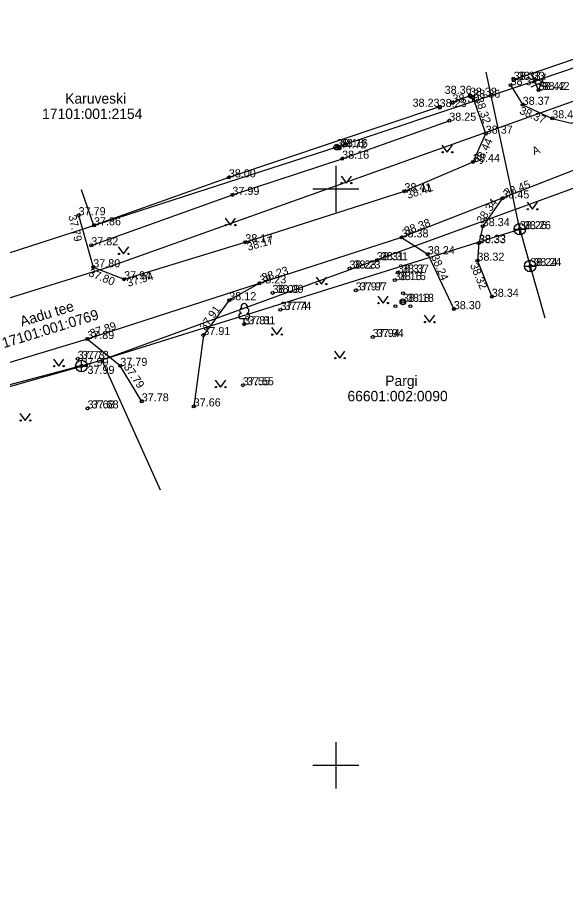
# Model space of a CAD drawing. Extents: x 627548 to 628052, y 6467984 to 6468802.
# Drawn here: x 627722.4 to 627769.9, y 6468388.4 to 6468464.9 of the extents above; entities that cross this region are included whole.
import ezdxf

# ---------------------------------------------------------------- set-up
doc = ezdxf.new("R2010")
doc.units = 0
for name, color, linetype in [('AED', 7, 'Continuous'), ('HALJASTUS', 7, 'Continuous'), ('KKAEV', 7, 'Continuous'), ('KORGUS-EH2000', 7, 'Continuous'), ('KTRASS', 7, 'Continuous'), ('MOOTKORG-EH2000', 7, 'Continuous'), ('MOOTKORGMUU-EH2000', 7, 'Continuous'), ('MOOTMPUNKT', 7, 'Continuous'), ('MPOHULIIN', 7, 'Continuous'), ('PIIR', 7, 'Continuous'), ('POST', 7, 'Continuous'), ('PUU', 7, 'Continuous'), ('SIOHULIIN', 7, 'Continuous'), ('TEE', 7, 'Continuous'), ('VORK', 7, 'Continuous')]:
    doc.layers.add(name, color=color, linetype=linetype)

msp = doc.modelspace()

# ---------------------------------------------------------------- linework, layer by layer
at = {"layer": 'AED'}
for p, q in [((627765.315, 6468459.596), (627765.315, 6468459.346)), ((627765.315, 6468459.596), (627765.565, 6468459.596)), ((627765.565, 6468459.596), (627765.565, 6468459.346)), ((627765.315, 6468459.346), (627765.565, 6468459.346)), ((627761.635, 6468458.089), (627760.129, 6468457.507)), ((627761.51, 6468458.214), (627761.51, 6468457.964)), ((627761.51, 6468458.214), (627761.76, 6468458.214)), ((627761.51, 6468457.964), (627761.76, 6468457.964)), ((627761.76, 6468458.214), (627761.76, 6468457.964)), ((627758.89, 6468457.24), (627758.89, 6468456.99)), ((627758.89, 6468457.24), (627759.14, 6468457.24)), ((627759.14, 6468457.24), (627759.14, 6468456.99)), ((627760.004, 6468457.632), (627760.004, 6468457.382)), ((627760.004, 6468457.632), (627760.254, 6468457.632)), ((627760.004, 6468457.382), (627760.254, 6468457.382)), ((627760.254, 6468457.632), (627760.254, 6468457.382)), ((627758.89, 6468456.99), (627759.14, 6468456.99))]:
    msp.add_line(p, q, dxfattribs=at)
for points in [[(627793.589, 6468469.234), (627785.422, 6468466.301), (627773.403, 6468462.19), (627765.44, 6468459.471)], [(627759.015, 6468457.115), (627740.72, 6468451.002), (627729.018, 6468446.845), (627727.922, 6468449.929)]]:
    msp.add_lwpolyline(points, dxfattribs=at)
at = {"layer": 'HALJASTUS'}
for p, q in [((627759.218, 6468453.793), (627759.682, 6468453.187)), ((627759.682, 6468453.187), (627760.127, 6468453.793)), ((627750.461, 6468451.119), (627750.924, 6468450.512)), ((627750.924, 6468450.512), (627751.37, 6468451.119)), ((627766.611, 6468448.843), (627767.074, 6468448.236)), ((627767.074, 6468448.236), (627767.52, 6468448.843)), ((627740.395, 6468447.478), (627740.859, 6468446.871)), ((627740.859, 6468446.871), (627741.304, 6468447.478)), ((627731.126, 6468444.974), (627731.589, 6468444.367)), ((627731.589, 6468444.367), (627732.035, 6468444.974)), ((627748.3, 6468442.357), (627748.763, 6468441.75)), ((627748.763, 6468441.75), (627749.209, 6468442.357)), ((627753.645, 6468440.707), (627754.109, 6468440.1)), ((627754.109, 6468440.1), (627754.554, 6468440.707)), ((627757.683, 6468439.057), (627758.146, 6468438.45)), ((627758.146, 6468438.45), (627758.592, 6468439.057)), ((627744.433, 6468437.975), (627744.896, 6468437.369)), ((627744.896, 6468437.369), (627745.342, 6468437.975)), ((627749.892, 6468435.927), (627750.356, 6468435.32)), ((627750.356, 6468435.32), (627750.801, 6468435.927)), ((627725.496, 6468435.244), (627725.96, 6468434.638)), ((627725.96, 6468434.638), (627726.405, 6468435.244)), ((627739.542, 6468433.424), (627740.006, 6468432.817)), ((627740.006, 6468432.817), (627740.451, 6468433.424)), ((627722.596, 6468430.522), (627723.059, 6468429.915)), ((627723.059, 6468429.915), (627723.505, 6468430.522))]:
    msp.add_line(p, q, dxfattribs=at)
for centre in [(627759.281, 6468453.187), (627760.109, 6468453.187), (627750.523, 6468450.512), (627751.352, 6468450.512), (627766.673, 6468448.236), (627767.502, 6468448.236), (627740.458, 6468446.871), (627741.287, 6468446.871), (627731.188, 6468444.367), (627732.017, 6468444.367), (627748.362, 6468441.75), (627749.191, 6468441.75), (627753.708, 6468440.1), (627754.537, 6468440.1), (627757.745, 6468438.45), (627758.574, 6468438.45), (627744.495, 6468437.369), (627745.324, 6468437.369), (627749.955, 6468435.32), (627750.783, 6468435.32), (627725.559, 6468434.638), (627726.387, 6468434.638), (627739.605, 6468432.817), (627740.434, 6468432.817), (627722.658, 6468429.915), (627723.487, 6468429.915)]:
    msp.add_circle(centre, 0.055, dxfattribs=at)
at = {"layer": 'KKAEV'}
for p, q in [((627765.476, 6468446.513), (627766.476, 6468446.513)), ((627765.976, 6468446.013), (627765.976, 6468447.013)), ((627766.878, 6468442.815), (627766.878, 6468443.815)), ((627766.378, 6468443.315), (627767.378, 6468443.315)), ((627727.929, 6468434.138), (627727.929, 6468435.138)), ((627727.429, 6468434.638), (627728.429, 6468434.638))]:
    msp.add_line(p, q, dxfattribs=at)
for centre in [(627765.976, 6468446.513), (627766.878, 6468443.315), (627727.929, 6468434.638)]:
    msp.add_circle(centre, 0.5, dxfattribs=at)
at = {"layer": 'KTRASS'}
msp.add_line((627765.976, 6468446.513), (627763.045, 6468460.12), dxfattribs=at)
msp.add_lwpolyline([(627653.907, 6468388.368), (627643.967, 6468406.571), (627696.734, 6468425.803), (627727.929, 6468434.638), (627765.976, 6468446.513), (627766.878, 6468443.315), (627768.149, 6468438.807)], dxfattribs=at)
at = {"layer": 'MOOTMPUNKT'}
for centre in [(627765.44, 6468459.471), (627765.165, 6468459.007), (627767.597, 6468458.583), (627761.635, 6468458.089), (627761.937, 6468457.914), (627759.015, 6468457.115), (627760.129, 6468457.507), (627766.223, 6468457.303), (627759.851, 6468455.919), (627768.784, 6468456.128), (627763.015, 6468454.798), (627750.093, 6468453.636), (627750.336, 6468453.529), (627750.557, 6468452.624), (627761.916, 6468452.344), (627740.72, 6468451.002), (627741.031, 6468449.484), (627755.959, 6468449.801), (627764.457, 6468449.184), (627727.686, 6468447.721), (627729.018, 6468446.845), (627762.755, 6468446.775), (627765.976, 6468446.513), (627755.708, 6468445.797), (627728.782, 6468445.109), (627742.149, 6468445.377), (627762.41, 6468445.297), (627762.43, 6468445.327), (627757.987, 6468444.338), (627753.569, 6468443.816), (627762.293, 6468443.775), (627766.878, 6468443.315), (627728.953, 6468443.206), (627751.19, 6468443.098), (627755.401, 6468442.746), (627731.631, 6468442.165), (627743.362, 6468441.806), (627755.123, 6468442.092), (627744.517, 6468440.979), (627751.737, 6468441.197), (627740.758, 6468440.345), (627755.828, 6468440.207), (627763.543, 6468440.641), (627745.196, 6468439.512), (627760.245, 6468439.571), (627742.057, 6468438.259), (627738.51, 6468437.327), (627753.206, 6468437.151), (627728.433, 6468436.983), (627727.606, 6468435.254), (627727.929, 6468434.638), (627731.305, 6468434.655), (627741.937, 6468432.968), (627733.163, 6468431.571), (627737.672, 6468431.136), (627728.46, 6468430.96)]:
    msp.add_circle(centre, 0.125, dxfattribs=at)
at = {"layer": 'MPOHULIIN'}
for points in [[(627776.772, 6468462.547), (627750.093, 6468453.636)], [(627750.093, 6468453.636), (627697.787, 6468436.749)]]:
    msp.add_lwpolyline(points, dxfattribs=at)
at = {"layer": 'PIIR'}
for p, q in [((627796.61, 6468466.88), (627730.27, 6468443.22)), ((627775.14, 6468451.7), (627729.69, 6468435.15)), ((627730.27, 6468443.22), (627696.02, 6468432.54)), ((627697.47, 6468426.57), (627729.69, 6468435.15)), ((627729.69, 6468435.15), (627734.759, 6468423.889))]:
    msp.add_line(p, q, dxfattribs=at)
at = {"layer": 'POST'}
for radius in [0.25, 0.0234]:
    msp.add_circle((627750.093, 6468453.636), radius, dxfattribs=at)
at = {"layer": 'PUU'}
for p, q in [((627767.597, 6468458.583), (627766.976, 6468460.03)), ((627767.301, 6468459.653), (627767.025, 6468459.535)), ((627767.597, 6468458.583), (627768.218, 6468460.03)), ((627767.893, 6468459.653), (627768.169, 6468459.535)), ((627767.597, 6468459.127), (627766.94, 6468458.845)), ((627767.557, 6468459.436), (627767.006, 6468459.2)), ((627767.597, 6468459.127), (627768.254, 6468458.845)), ((627767.637, 6468459.436), (627768.188, 6468459.2)), ((627767.957, 6468458.583), (627767.597, 6468458.583)), ((627742.297, 6468438.734), (627741.817, 6468438.734)), ((627742.057, 6468438.259), (627742.057, 6468438.734)), ((627742.437, 6468438.259), (627742.057, 6468438.259))]:
    msp.add_line(p, q, dxfattribs=at)
msp.add_lwpolyline([(627728.782, 6468445.109), (627741.031, 6468449.484), (627750.557, 6468452.624), (627759.851, 6468455.919)], dxfattribs=at)
for centre, radius in [((627755.828, 6468440.207), 0.25), ((627755.828, 6468440.957), 0.125), ((627755.178, 6468439.832), 0.125), ((627756.478, 6468439.832), 0.125)]:
    msp.add_circle(centre, radius, dxfattribs=at)
for centre, radius, start, end in [((627741.887, 6468439.432), 0.233, 109.02174, 253.14154), ((627742.057, 6468439.779), 0.277, 332.5799, 207.4201), ((627742.227, 6468439.432), 0.233, 286.85082, 70.98591), ((627741.82, 6468438.971), 0.238, 90.0016, 269.3953), ((627742.294, 6468438.971), 0.238, 270.6047, 89.9984)]:
    msp.add_arc(centre, radius, start, end, dxfattribs=at)
at = {"layer": 'SIOHULIIN'}
for points in [[(627776.772, 6468462.547), (627750.093, 6468453.636)], [(627750.093, 6468453.636), (627697.787, 6468436.749)]]:
    msp.add_lwpolyline(points, dxfattribs=at)
at = {"layer": 'TEE'}
for points in [[(627765.165, 6468459.007), (627766.223, 6468457.303), (627768.784, 6468456.128), (627770.445, 6468455.699), (627773.709, 6468456.834), (627786.129, 6468461.455), (627794.971, 6468465.055)], [(627796.263, 6468461.011), (627787.58, 6468457.698), (627775.784, 6468453.617), (627755.708, 6468445.797), (627743.362, 6468441.806), (627728.433, 6468436.983), (627717.465, 6468433.665), (627699.12, 6468428.233), (627696.098, 6468427.452), (627683.485, 6468423.1), (627674.185, 6468419.981), (627673.482, 6468419.039), (627673.355, 6468417.806)], [(627727.686, 6468447.721), (627728.953, 6468443.206), (627731.631, 6468442.165), (627742.149, 6468445.377), (627755.959, 6468449.801), (627761.916, 6468452.344), (627763.015, 6468454.798), (627761.937, 6468457.914)], [(627764.457, 6468449.184), (627762.755, 6468446.775), (627762.41, 6468445.297)], [(627755.708, 6468445.797), (627757.987, 6468444.338), (627760.245, 6468439.571)], [(627762.43, 6468445.327), (627762.293, 6468443.775), (627763.543, 6468440.641)], [(627743.362, 6468441.806), (627740.758, 6468440.345), (627738.51, 6468437.327), (627737.672, 6468431.136)], [(627733.163, 6468431.571), (627731.305, 6468434.655), (627728.433, 6468436.983)]]:
    msp.add_lwpolyline(points, dxfattribs=at)
at = {"layer": 'VORK'}
for p, q in [((627750, 6468452), (627750, 6468448)), ((627748, 6468450), (627752, 6468450)), ((627750, 6468402), (627750, 6468398)), ((627748, 6468400), (627752, 6468400))]:
    msp.add_line(p, q, dxfattribs=at)

# ---------------------------------------------------------------- texts
at = {"layer": 'KORGUS-EH2000'}
for s, p in [('38.33', (627765.79, 6468459.471)), ('38.36', (627759.453, 6468458.252)), ('38.42', (627767.947, 6468458.583)), ('38.23', (627756.666, 6468457.132)), ('38.16', (627750.443, 6468453.636)), ('38.26', (627766.326, 6468446.513)), ('38.31', (627753.919, 6468443.816)), ('38.23', (627751.54, 6468443.098)), ('38.37', (627755.751, 6468442.746)), ('38.24', (627767.228, 6468443.315)), ('38.16', (627755.473, 6468442.092)), ('37.97', (627752.087, 6468441.197)), ('38.09', (627744.867, 6468440.979)), ('38.18', (627756.178, 6468440.207)), ('37.74', (627745.546, 6468439.512)), ('37.81', (627742.407, 6468438.259)), ('37.94', (627753.556, 6468437.151)), ('37.73', (627727.956, 6468435.254)), ('37.99', (627728.454, 6468433.957)), ('37.55', (627742.287, 6468432.968)), ('37.68', (627728.81, 6468430.96))]:
    msp.add_text(s, height=0.7, dxfattribs=at).set_placement(p)
for s, rotation, p in [('38.32', 288.4265, (627762.092, 6468457.819)), ('38.37', 336.84443, (627765.881, 6468456.55)), ('38.44', 65.02025, (627762.649, 6468452.073)), ('38.41', 17.86391, (627756.279, 6468449.128)), ('38.45', 20.90876, (627764.777, 6468449.301)), ('38.34', 54.92768, (627762.724, 6468446.927)), ('37.79', 283.30243, (627726.79, 6468447.659)), ('38.38', 20.35359, (627756.092, 6468445.993)), ('38.17', 15.4544, (627742.41, 6468444.635)), ('38.24', 293.5654, (627758.253, 6468444.128)), ('38.32', 292.72202, (627761.641, 6468443.392)), ('37.80', 338.08707, (627728.484, 6468442.473)), ('37.94', 16.11404, (627731.988, 6468441.493)), ('38.23', 17.14213, (627743.711, 6468441.952)), ('37.91', 54.34495, (627738.674, 6468437.667)), ('37.89', 17.97702, (627728.791, 6468437.116)), ('37.79', 304.23353, (627731.559, 6468434.562))]:
    msp.add_text(s, height=0.7, rotation=rotation, dxfattribs=at).set_placement(p)
at = {"layer": 'MOOTKORG-EH2000'}
for s, p in [('38.34', (627765.165, 6468459.007)), ('38.33', (627765.44, 6468459.471)), ('38.32', (627761.635, 6468458.089)), ('38.42', (627767.597, 6468458.583)), ('38.30', (627760.129, 6468457.507)), ('38.36', (627761.937, 6468457.914)), ('38.37', (627766.223, 6468457.303)), ('38.23', (627759.015, 6468457.115)), ('38.25', (627759.851, 6468455.919)), ('38.41', (627768.784, 6468456.128)), ('38.37', (627763.015, 6468454.798)), ('38.16', (627750.093, 6468453.636)), ('38.16', (627750.557, 6468452.624)), ('38.44', (627761.916, 6468452.344)), ('38.00', (627740.72, 6468451.002)), ('38.41', (627755.959, 6468449.801)), ('37.99', (627741.031, 6468449.484)), ('38.45', (627764.457, 6468449.184)), ('37.79', (627727.686, 6468447.721)), ('37.86', (627729.018, 6468446.845)), ('38.34', (627762.755, 6468446.775)), ('38.26', (627765.976, 6468446.513)), ('38.38', (627755.708, 6468445.797)), ('37.82', (627728.782, 6468445.109)), ('38.17', (627742.149, 6468445.377)), ('38.33', (627762.41, 6468445.297)), ('38.33', (627762.43, 6468445.327)), ('38.24', (627757.987, 6468444.338)), ('38.31', (627753.569, 6468443.816)), ('38.32', (627762.293, 6468443.775)), ('37.80', (627728.953, 6468443.206)), ('38.23', (627751.19, 6468443.098)), ('38.37', (627755.401, 6468442.746)), ('38.24', (627766.878, 6468443.315)), ('37.94', (627731.631, 6468442.165)), ('38.16', (627755.123, 6468442.092)), ('38.23', (627743.362, 6468441.806)), ('37.97', (627751.737, 6468441.197)), ('38.09', (627744.517, 6468440.979)), ('38.34', (627763.543, 6468440.641)), ('38.12', (627740.758, 6468440.345)), ('38.18', (627755.828, 6468440.207)), ('37.74', (627745.196, 6468439.512)), ('38.30', (627760.245, 6468439.571)), ('37.81', (627742.057, 6468438.259)), ('37.91', (627738.51, 6468437.327)), ('37.89', (627728.433, 6468436.983)), ('37.94', (627753.206, 6468437.151)), ('37.73', (627727.606, 6468435.254)), ('37.99', (627727.929, 6468434.638)), ('37.79', (627731.305, 6468434.655)), ('37.55', (627741.937, 6468432.968)), ('37.78', (627733.163, 6468431.571)), ('37.68', (627728.46, 6468430.96)), ('37.66', (627737.672, 6468431.136))]:
    msp.add_text(s, height=0.7, dxfattribs=at).set_placement(p)
at = {"layer": 'MOOTKORGMUU-EH2000'}
msp.add_text('44.72', height=0.7, dxfattribs=at).set_placement((627750.336, 6468453.529))
at = {"layer": 'PIIR'}
for s, p in [('Karuveski', (627726.523, 6468457.403)), ('17101:001:2154', (627724.516, 6468456.072)), ('Pargi', (627754.298, 6468432.912)), ('66601:002:0090', (627751.015, 6468431.581))]:
    msp.add_text(s, height=0.9, dxfattribs=at).set_placement(p)
for s, p in [('Aadu tee', (627722.754, 6468438.045)), ('17101:001:0769', (627721.188, 6468436.174))]:
    msp.add_text(s, height=0.9, rotation=17.03041, dxfattribs=at).set_placement(p)
at = {"layer": 'TEE'}
msp.add_text('A', height=0.7, rotation=23.80727, dxfattribs=at).set_placement((627767.225, 6468452.908))

doc.saveas('drawing.dxf')
